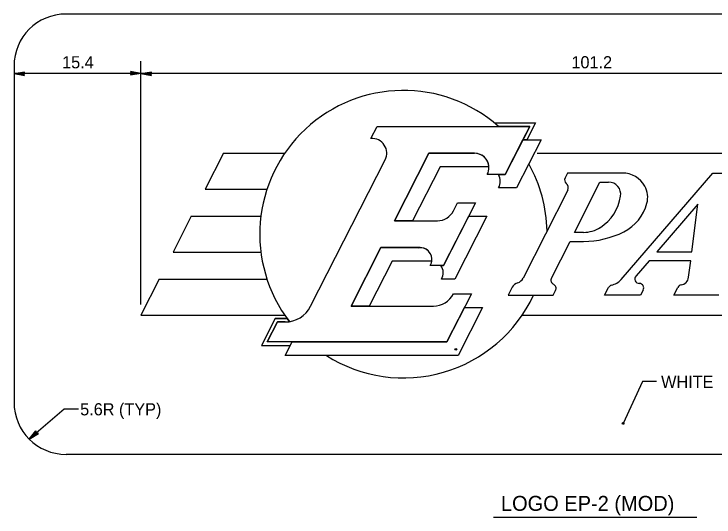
# Model space of a CAD drawing. Extents: x 10268197 to 10269179, y 2141503 to 2142677.
# Drawn here: x 10268666.98 to 10268707.32, y 2142208.74 to 2142237.72 of the extents above; entities that cross this region are included whole.
import ezdxf

# ---------------------------------------------------------------- set-up
doc = ezdxf.new("R2010")
doc.units = 0
for name, color, linetype in [('1', 7, 'Continuous'), ('2', 7, 'Continuous'), ('21', 7, 'Continuous'), ('3', 7, 'Continuous')]:
    doc.layers.add(name, color=color, linetype=linetype)

msp = doc.modelspace()

# ---------------------------------------------------------------- linework, layer by layer
at = {"layer": '1'}
for p, q in [((10268674.298, 2142220.985), (10268674.298, 2142234.996)), ((10268673.741, 2142234.302), (10268673.693, 2142234.196)), ((10268674.298, 2142234.292), (10268673.693, 2142234.196)), ((10268674.298, 2142234.292), (10268673.696, 2142234.409)), ((10268673.696, 2142234.409), (10268673.741, 2142234.302)), ((10268674.298, 2142234.292), (10268673.719, 2142234.252)), ((10268674.298, 2142234.292), (10268673.72, 2142234.353)), ((10268695.292, 2142228.473), (10268696.308, 2142230.466)), ((10268697.354, 2142230.466), (10268695.943, 2142227.699)), ((10268696.308, 2142230.466), (10268697.354, 2142230.466)), ((10268688.91, 2142225.809), (10268690.887, 2142229.69)), ((10268690.887, 2142229.69), (10268693.525, 2142229.69)), ((10268691.537, 2142228.914), (10268689.955, 2142225.809)), ((10268694.352, 2142228.914), (10268691.537, 2142228.914)), ((10268694.908, 2142228.473), (10268695.292, 2142228.473)), ((10268695.943, 2142227.699), (10268694.908, 2142227.699)), ((10268689.955, 2142225.809), (10268688.91, 2142225.809)), ((10268691.737, 2142223.221), (10268693.187, 2142226.067)), ((10268694.232, 2142226.067), (10268692.387, 2142222.444)), ((10268693.187, 2142226.067), (10268694.232, 2142226.067)), ((10268686.405, 2142220.892), (10268688.119, 2142224.256)), ((10268688.119, 2142224.256), (10268690.292, 2142224.248)), ((10268688.768, 2142223.478), (10268687.45, 2142220.892)), ((10268691.053, 2142223.47), (10268688.768, 2142223.478)), ((10268691.574, 2142223.221), (10268691.737, 2142223.221)), ((10268692.387, 2142222.444), (10268691.611, 2142222.444)), ((10268687.45, 2142220.892), (10268686.405, 2142220.892)), ((10268691.928, 2142218.821), (10268692.942, 2142220.812)), ((10268693.988, 2142220.812), (10268692.578, 2142218.045)), ((10268692.942, 2142220.812), (10268693.988, 2142220.812)), ((10268682.612, 2142218.045), (10268683.008, 2142218.821)), ((10268683.008, 2142218.821), (10268691.928, 2142218.821)), ((10268692.578, 2142218.045), (10268682.612, 2142218.045)), ((10268703.196, 2142216.536), (10268702.081, 2142214.129)), ((10268704.018, 2142216.536), (10268703.196, 2142216.536)), ((10268669.869, 2142214.957), (10268667.857, 2142213.226)), ((10268670.691, 2142214.957), (10268669.869, 2142214.957))]:
    msp.add_line(p, q, dxfattribs=at)
msp.add_lwpolyline([(10268694.667, 2142231.443), (10268697.039, 2142231.443), (10268696.541, 2142230.466), (10268696.308, 2142230.466), (10268696.704, 2142231.243), (10268694.903, 2142231.243)], close=True, dxfattribs=at)
for centre in [(10268692.445, 2142218.399), (10268702.081, 2142214.129)]:
    msp.add_circle(centre, 0.0518, dxfattribs=at)
for centre, radius, start, end in [((10268693.526, 2142228.862), 0.828, 3.5833, 90), ((10268694.176, 2142228.086), 0.828, 332.2089, 27.9127), ((10268690.39, 2142223.583), 0.673, 350.3502, 98.3344), ((10268691.044, 2142222.807), 0.673, 327.421, 37.9799)]:
    msp.add_arc(centre, radius, start, end, dxfattribs=at)
at = {"layer": '2'}
for p, q in [((10268730.979, 2142237.716), (10268669.979, 2142237.716)), ((10268666.979, 2142234.716), (10268666.979, 2142215.347)), ((10268674.298, 2142234.292), (10268666.979, 2142234.292)), ((10268726.659, 2142234.292), (10268674.298, 2142234.292)), ((10268694.667, 2142231.443), (10268697.039, 2142231.443)), ((10268697.039, 2142231.443), (10268696.541, 2142230.466)), ((10268687.552, 2142230.549), (10268687.905, 2142231.243)), ((10268687.905, 2142231.243), (10268696.704, 2142231.243)), ((10268696.704, 2142231.243), (10268695.294, 2142228.476)), ((10268695.292, 2142228.473), (10268696.308, 2142230.466)), ((10268697.354, 2142230.466), (10268695.943, 2142227.699)), ((10268696.308, 2142230.466), (10268697.354, 2142230.466)), ((10268679.045, 2142229.69), (10268677.99, 2142227.62)), ((10268679.045, 2142229.69), (10268682.579, 2142229.69)), ((10268690.887, 2142229.69), (10268688.91, 2142225.809)), ((10268688.91, 2142225.809), (10268690.887, 2142229.69)), ((10268693.525, 2142229.69), (10268690.887, 2142229.69)), ((10268690.887, 2142229.69), (10268693.525, 2142229.69)), ((10268697.136, 2142229.69), (10268726.659, 2142229.69)), ((10268684.075, 2142220.879), (10268688.369, 2142229.309)), ((10268691.537, 2142228.914), (10268689.955, 2142225.809)), ((10268694.352, 2142228.914), (10268691.537, 2142228.914)), ((10268698.881, 2142228.551), (10268698.74, 2142228.273)), ((10268702.051, 2142228.551), (10268698.881, 2142228.551)), ((10268701.971, 2142222.427), (10268707.256, 2142228.551)), ((10268707.256, 2142228.551), (10268708.188, 2142228.551)), ((10268695.294, 2142228.476), (10268694.258, 2142228.476)), ((10268694.908, 2142228.473), (10268695.292, 2142228.473)), ((10268699.288, 2142225.136), (10268700.752, 2142228.03)), ((10268700.752, 2142228.03), (10268701.251, 2142228.03)), ((10268677.99, 2142227.62), (10268681.559, 2142227.62)), ((10268695.943, 2142227.699), (10268694.908, 2142227.699)), ((10268698.89, 2142227.566), (10268696.328, 2142222.499)), ((10268693.582, 2142226.844), (10268691.737, 2142223.221)), ((10268692.307, 2142226.374), (10268692.548, 2142226.844)), ((10268692.548, 2142226.844), (10268693.582, 2142226.844)), ((10268706.39, 2142226.753), (10268704.027, 2142224.015)), ((10268706.037, 2142224.015), (10268706.39, 2142226.753)), ((10268677.199, 2142226.067), (10268676.144, 2142223.997)), ((10268677.199, 2142226.067), (10268681.21, 2142226.067)), ((10268688.91, 2142225.809), (10268691.386, 2142225.809)), ((10268689.955, 2142225.809), (10268688.91, 2142225.809)), ((10268691.737, 2142223.221), (10268693.187, 2142226.067)), ((10268694.232, 2142226.067), (10268692.387, 2142222.444)), ((10268693.187, 2142226.067), (10268694.232, 2142226.067)), ((10268699.8, 2142225.136), (10268699.288, 2142225.136)), ((10268697.954, 2142222.5), (10268699.024, 2142224.615)), ((10268699.024, 2142224.615), (10268699.8, 2142224.615)), ((10268688.119, 2142224.256), (10268686.405, 2142220.892)), ((10268686.405, 2142220.892), (10268688.119, 2142224.256)), ((10268690.39, 2142224.256), (10268688.119, 2142224.256)), ((10268688.119, 2142224.256), (10268690.292, 2142224.248)), ((10268676.144, 2142223.997), (10268681.21, 2142223.997)), ((10268704.027, 2142224.015), (10268706.037, 2142224.015)), ((10268688.768, 2142223.478), (10268687.45, 2142220.892)), ((10268691.053, 2142223.47), (10268688.768, 2142223.478)), ((10268703.579, 2142223.494), (10268702.828, 2142222.624)), ((10268705.984, 2142223.494), (10268703.579, 2142223.494)), ((10268705.861, 2142222.551), (10268705.984, 2142223.494)), ((10268691.737, 2142223.221), (10268690.957, 2142223.221)), ((10268691.574, 2142223.221), (10268691.737, 2142223.221)), ((10268675.353, 2142222.444), (10268674.298, 2142220.374)), ((10268675.353, 2142222.444), (10268681.559, 2142222.444)), ((10268692.387, 2142222.444), (10268691.611, 2142222.444)), ((10268695.699, 2142221.973), (10268695.466, 2142221.513)), ((10268698.054, 2142221.513), (10268698.195, 2142221.791)), ((10268701.019, 2142221.512), (10268701.244, 2142221.958)), ((10268703.242, 2142221.814), (10268703.089, 2142221.512)), ((10268705.014, 2142221.512), (10268705.242, 2142221.965)), ((10268693.338, 2142221.588), (10268691.928, 2142218.821)), ((10268692.302, 2142221.588), (10268693.338, 2142221.588)), ((10268695.466, 2142221.513), (10268698.054, 2142221.513)), ((10268703.089, 2142221.512), (10268701.019, 2142221.512)), ((10268707.601, 2142221.512), (10268705.014, 2142221.512)), ((10268686.405, 2142220.892), (10268691.154, 2142220.892)), ((10268687.45, 2142220.892), (10268686.405, 2142220.892)), ((10268691.928, 2142218.821), (10268692.942, 2142220.812)), ((10268693.988, 2142220.812), (10268692.578, 2142218.045)), ((10268692.942, 2142220.812), (10268693.988, 2142220.812)), ((10268674.298, 2142220.374), (10268682.579, 2142220.374)), ((10268682.037, 2142220.182), (10268681.24, 2142218.614)), ((10268682.037, 2142220.182), (10268682.714, 2142220.182)), ((10268696.271, 2142220.374), (10268721.913, 2142220.374)), ((10268681.578, 2142218.821), (10268682.164, 2142219.974)), ((10268682.164, 2142219.974), (10268681.578, 2142218.821)), ((10268682.599, 2142219.975), (10268682.164, 2142219.974)), ((10268682.164, 2142219.974), (10268682.599, 2142219.974)), ((10268681.24, 2142218.614), (10268682.902, 2142218.614)), ((10268691.928, 2142218.821), (10268681.578, 2142218.821)), ((10268682.612, 2142218.045), (10268683.008, 2142218.821)), ((10268683.008, 2142218.821), (10268691.928, 2142218.821)), ((10268692.578, 2142218.045), (10268682.612, 2142218.045)), ((10268730.979, 2142212.347), (10268669.979, 2142212.347))]:
    msp.add_line(p, q, dxfattribs=at)
for centre, radius, start, end in [((10268669.979, 2142234.716), 3, 90, 180), ((10268689.425, 2142225.032), 8.281, 48.5904, 217.4725), ((10268687.609, 2142229.697), 0.854, 332.9998, 93.8045), ((10268693.526, 2142228.862), 0.828, 332.2089, 90), ((10268693.526, 2142228.862), 0.828, 3.5833, 90), ((10268689.425, 2142225.032), 8.281, 1.2967, 29.2778), ((10268694.176, 2142228.086), 0.828, 332.2089, 27.9127), ((10268691.386, 2142226.844), 1.035, 270, 332.9883), ((10268690.39, 2142223.583), 0.673, 350.3502, 98.3344), ((10268690.39, 2142223.583), 0.673, 327.421, 90), ((10268691.044, 2142222.807), 0.673, 327.421, 37.9799), ((10268689.425, 2142225.032), 8.281, 237.5383, 334.8493), ((10268691.154, 2142222.186), 1.294, 270, 332.5096), ((10268682.599, 2142221.631), 1.656, 270, 332.9991), ((10268669.979, 2142215.347), 3, 180, 270)]:
    msp.add_arc(centre, radius, start, end, dxfattribs=at)
for centre, major_axis, start_param, end_param in [((10268702.051, 2142227.066), (0, 1.486), 5.226065, 6.283185), ((10268698.971, 2142228.155), (0, -0.261), 4.240773, 5.605302), ((10268698.614, 2142227.708), (0, -0.313), 1.099604, 2.46371), ((10268701.25, 2142227.326), (0, -0.704), 1.415043, 3.141593), ((10268702.209, 2142227.155), (0, 1.303), 4.445482, 5.226065), ((10268699.384, 2142227.622), (0, -2.607), 0.565847, 1.415043), ((10268700.961, 2142227.499), (0, -2.607), 0.465011, 1.30389), ((10268699.8, 2142226.961), (0, -1.825), 0, 0.565847), ((10268699.8, 2142229.829), (0, -5.214), 0, 0.465011), ((10268695.867, 2142222.736), (0, -0.521), 0.286787, 1.099486), ((10268698.184, 2142222.381), (0, 0.261), 1.099355, 2.701477), ((10268703.024, 2142222.454), (0, 0.261), 0.854904, 3.118676), ((10268705.348, 2142222.619), (0, -0.521), 0.161263, 1.440999), ((10268696.16, 2142221.736), (0, -0.521), 3.428379, 4.240701), ((10268697.964, 2142221.91), (0, 0.261), 4.241567, 5.84307), ((10268701.475, 2142221.84), (0, -0.261), 3.363532, 4.241567), ((10268701.191, 2142223.112), (0, -1.043), 0.22194, 0.855152), ((10268703.012, 2142221.932), (0, 0.261), 4.240773, 6.260268), ((10268705.473, 2142221.847), (0, -0.261), 3.302856, 4.241567)]:
    msp.add_ellipse(centre, major_axis=major_axis, ratio=0.992614, start_param=start_param, end_param=end_param, dxfattribs=at)
at = {"layer": '21'}
for p, q in [((10268666.979, 2142234.292), (10268667.584, 2142234.388)), ((10268666.979, 2142234.292), (10268667.559, 2142234.333)), ((10268666.979, 2142234.292), (10268667.58, 2142234.175)), ((10268666.979, 2142234.292), (10268667.557, 2142234.232)), ((10268667.536, 2142234.283), (10268667.584, 2142234.388)), ((10268667.58, 2142234.175), (10268667.536, 2142234.283)), ((10268674.298, 2142234.292), (10268674.904, 2142234.388)), ((10268674.298, 2142234.292), (10268674.878, 2142234.333)), ((10268674.298, 2142234.292), (10268674.9, 2142234.175)), ((10268674.298, 2142234.292), (10268674.877, 2142234.232)), ((10268674.856, 2142234.283), (10268674.904, 2142234.388)), ((10268674.9, 2142234.175), (10268674.856, 2142234.283)), ((10268667.857, 2142213.226), (10268668.245, 2142213.7)), ((10268667.857, 2142213.226), (10268668.263, 2142213.642)), ((10268668.28, 2142213.59), (10268668.245, 2142213.7)), ((10268667.857, 2142213.226), (10268668.329, 2142213.566)), ((10268667.857, 2142213.226), (10268668.384, 2142213.539)), ((10268668.384, 2142213.539), (10268668.28, 2142213.59)), ((10268694.619, 2142208.738), (10268706.338, 2142208.738))]:
    msp.add_line(p, q, dxfattribs=at)
at = {"layer": '3'}
msp.add_lwpolyline([(10268682.714, 2142220.182), (10268682.037, 2142220.182), (10268681.24, 2142218.614), (10268682.902, 2142218.614), (10268683.008, 2142218.821), (10268681.578, 2142218.821), (10268682.164, 2142219.974), (10268682.599, 2142219.974), (10268682.853, 2142219.994)], close=True, dxfattribs=at)

# ---------------------------------------------------------------- texts
at = {"layer": '1'}
for s, height, p in [('15.4', 0.7, (10268669.751, 2142234.587)), ('101.2', 0.7, (10268699.105, 2142234.587)), ('WHITE', 0.7, (10268704.274, 2142216.173)), ('5.6R (TYP)', 0.7, (10268670.792, 2142214.594)), ('LOGO EP-2 (MOD)', 0.8624, (10268695.043, 2142209.092))]:
    msp.add_text(s, height=height, dxfattribs=at).set_placement(p)

doc.saveas('drawing.dxf')
